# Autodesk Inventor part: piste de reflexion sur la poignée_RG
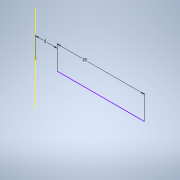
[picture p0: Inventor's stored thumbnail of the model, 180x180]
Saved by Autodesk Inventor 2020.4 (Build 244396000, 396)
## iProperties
Created: 2021-10
Part Number: piste de reflexion sur la poignée_RG
Material: Générique
Document SubType Name: Modeling
Designer: mel
Density: 1 g/cm^3
Appearance: Par défaut
Author: mel
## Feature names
1. Balayage1
2. Révolution1 [Revolution]
3. Extrusion1
4. Lissage1
## Parameters: d0 = 0, d2 = 5 mm, d3 = 4 mm, d4 = 0, d5 = 0, d6 = 4 mm, d7 = 4 mm, d8 = 180 deg, d9 = 4 mm, d10 = 4 mm, d11 = 0, d13 = 2 mm, d14 = 2 mm, d15 = 87 deg, d16 = 87 deg, d17 = 2 mm, d18 = 2 mm, d19 = 87 deg, d20 = 87 deg, d21 = 0, d22 = 90 deg, d23 = 0, d24 = 90 deg, d25 = 1 mm, d26 = 1 mm
